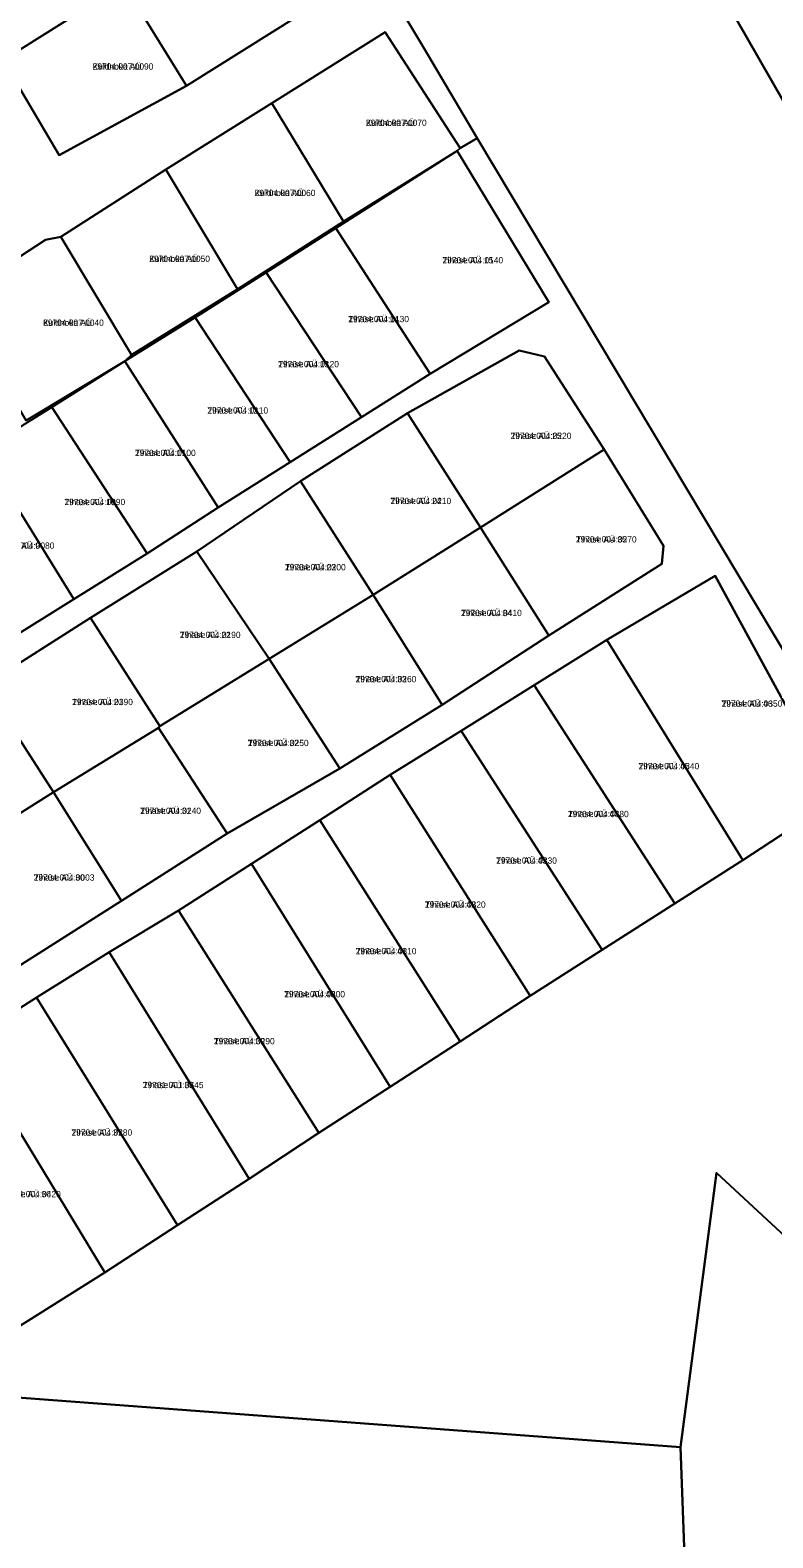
# Model space of a CAD drawing. Extents: x 504287 to 537970, y 6539941 to 6586214.
# Drawn here: x 516728.7 to 516906.1, y 6563396.7 to 6563756.4 of the extents above; entities that cross this region are included whole.
import ezdxf

# ---------------------------------------------------------------- set-up
doc = ezdxf.new("R2010")
doc.units = 0
for name, color, linetype in [('L_AADRESS', 7, 'Continuous'), ('PIIR', 7, 'Continuous'), ('TUNNUS', 7, 'Continuous')]:
    doc.layers.add(name, color=color, linetype=linetype)

msp = doc.modelspace()

# ---------------------------------------------------------------- linework, layer by layer
at = {"layer": 'PIIR'}
for points in [[(517379.78, 6562919.5), (517180.26, 6563268.51), (517112.27, 6563384.86), (516982.09, 6563611.59), (516744.27, 6564025.8), (516744.15, 6564026.01), (516730.68, 6564049.47), (516444.24, 6564548.52), (516445.68, 6564549.17), (516449.01, 6564550.8), (516452.43, 6564551.99), (516458.23, 6564554.15), (516464.7, 6564557.42), (516469.05, 6564559.51), (516471.43, 6564560.88), (516474.52, 6564562.81), (516484.15, 6564569.31), (516486.47, 6564571.24), (516492.75, 6564575.34), (517006.77, 6563683.7), (517111.59, 6563503.08), (517311.3, 6563151.72)], [(516814.57, 6563765.92), (516822.58, 6563752.44), (516835.52, 6563730.64), (516831.44, 6563728.29), (516813.56, 6563755.93), (516786.43, 6563739.01), (516761.12, 6563723.2), (516736.08, 6563707.11), (516732.39, 6563706.39), (516710.76, 6563692.3), (516685.1, 6563676.01), (516659.05, 6563660.05), (516626.42, 6563639.26), (516618.72, 6563651.98), (516652.8, 6563672.2), (516634.4, 6563701.07), (516617.19, 6563729.39), (516602.18, 6563753.59), (516591.84, 6563747.49), (516568.78, 6563733.94), (516566.1, 6563738.35), (516591.67, 6563753.24), (516617.83, 6563768.33)], [(516722.21, 6563610.11), (516739.21, 6563620.66), (516756.7, 6563631.52), (516773.62, 6563642.53), (516790.82, 6563653.37), (516807.85, 6563664.1), (516824.29, 6563674.45), (516852.61, 6563691.56), (516830.7, 6563727.62), (516831.44, 6563728.29), (516835.52, 6563730.64), (516927.25, 6563577.2)], [(516725.02, 6563532.42), (516750.56, 6563548.68), (516775.79, 6563564.73), (516802.71, 6563580.25), (516827.14, 6563595.44), (516852.62, 6563612.01), (516879.6, 6563629.07), (516880.04, 6563633.4), (516865.82, 6563656.34), (516851.54, 6563678.55), (516845.52, 6563679.99), (516818.88, 6563665.04), (516793.27, 6563648.79), (516768.52, 6563632.01), (516743.18, 6563616.21), (516717.81, 6563600.13)], [(516921.33, 6563573.01), (516892.36, 6563626.23), (516866.43, 6563610.95), (516849.15, 6563600.15), (516831.7, 6563589.26), (516814.75, 6563578.77), (516797.92, 6563567.94), (516781.58, 6563557.53), (516764.15, 6563546.36), (516747.57, 6563536.38), (516730.23, 6563525.6), (516713.3, 6563514.8), (516696.5, 6563504), (516670.97, 6563488.02), (516692.12, 6563446.36), (516625.46, 6563445.55), (516501.25, 6563444.05)]]:
    msp.add_lwpolyline(points, dxfattribs=at)
for points in [[(516744.27, 6564025.8), (516982.09, 6563611.59), (516927.25, 6563577.2), (516835.52, 6563730.64), (516822.58, 6563752.44), (516814.57, 6563765.92), (516798.6, 6563792.96), (516760.66, 6563855.96), (516742.75, 6563885.64), (516737.52, 6563882.87), (516722.3, 6563907.76), (516709.28, 6563929.6), (516697.15, 6563950.09), (516684.83, 6563970.67), (516672.52, 6563991.27), (516658.45, 6564008.29), (516673.61, 6564011.42), (516744.15, 6564026.01)], [(516722.29, 6563749.26), (516735.69, 6563726.63), (516766.07, 6563743.18), (516799.74, 6563764.29), (516785.62, 6563789.05), (516771.4, 6563813.09), (516757.06, 6563837.14), (516721.19, 6563815.1), (516692.06, 6563796.82), (516706.99, 6563772.95)], [(516706.99, 6563772.95), (516736.13, 6563791.14), (516751.12, 6563767.4), (516722.29, 6563749.26)], [(516751.12, 6563767.4), (516785.62, 6563789.05), (516799.74, 6563764.29), (516766.07, 6563743.18)], [(516722.29, 6563749.26), (516751.12, 6563767.4), (516766.07, 6563743.18), (516735.69, 6563726.63)], [(516813.56, 6563755.93), (516831.44, 6563728.29), (516830.7, 6563727.62), (516803.59, 6563710.81), (516786.43, 6563739.01)], [(516761.12, 6563723.2), (516786.43, 6563739.01), (516803.59, 6563710.81), (516778.28, 6563694.6)], [(516801.78, 6563709.16), (516830.7, 6563727.62), (516852.61, 6563691.56), (516824.29, 6563674.45)], [(516778.28, 6563694.6), (516752.91, 6563678.97), (516736.08, 6563707.1), (516761.12, 6563723.2)], [(516710.76, 6563692.3), (516732.39, 6563706.39), (516736.08, 6563707.1), (516752.91, 6563678.97), (516751.32, 6563677.47), (516727.82, 6563663.32)], [(516801.78, 6563709.16), (516824.29, 6563674.45), (516807.85, 6563664.1), (516785.14, 6563698.61)], [(516785.14, 6563698.61), (516807.85, 6563664.1), (516790.82, 6563653.37), (516768.11, 6563687.85)], [(516768.11, 6563687.85), (516790.82, 6563653.37), (516773.62, 6563642.53), (516751.32, 6563677.47)], [(516818.88, 6563665.04), (516845.52, 6563679.99), (516851.54, 6563678.55), (516865.82, 6563656.34), (516836.31, 6563637.79)], [(516751.32, 6563677.47), (516773.62, 6563642.53), (516756.7, 6563631.52), (516733.94, 6563666.48)], [(516733.94, 6563666.48), (516756.7, 6563631.52), (516739.21, 6563620.66), (516717.18, 6563656.16)], [(516793.27, 6563648.79), (516818.88, 6563665.04), (516836.31, 6563637.79), (516810.68, 6563621.65)], [(516702.36, 6563647.05), (516717.18, 6563656.16), (516739.21, 6563620.66), (516722.21, 6563610.11), (516700.84, 6563646.09)], [(516836.31, 6563637.79), (516865.82, 6563656.34), (516880.04, 6563633.4), (516879.6, 6563629.07), (516852.62, 6563612.01)], [(516768.52, 6563632.01), (516793.27, 6563648.79), (516810.68, 6563621.65), (516785.8, 6563606.44)], [(516836.31, 6563637.79), (516852.62, 6563612.01), (516827.14, 6563595.44), (516810.68, 6563621.65)], [(516743.18, 6563616.21), (516768.52, 6563632.01), (516785.8, 6563606.44), (516759.74, 6563590.32)], [(516892.36, 6563626.23), (516921.33, 6563573.01), (516898.91, 6563558.38), (516866.43, 6563610.95)], [(516810.68, 6563621.65), (516827.14, 6563595.44), (516802.71, 6563580.25), (516785.8, 6563606.44)], [(516743.18, 6563616.21), (516759.74, 6563590.32), (516759.36, 6563589.97), (516734.29, 6563574.56), (516717.81, 6563600.13)], [(516725.56, 6563446.76), (516746.61, 6563460.01), (516763.92, 6563471.26), (516781.08, 6563482.33), (516797.71, 6563493.29), (516814.71, 6563504.25), (516831.42, 6563515.11), (516848.12, 6563525.98), (516865.33, 6563536.97), (516882.68, 6563548.06), (516898.91, 6563558.38), (516921.33, 6563573.01), (516927.25, 6563577.2), (516982.09, 6563611.59), (517112.27, 6563384.86), (517064.02, 6563325.01), (516892.69, 6563483.77), (516884.06, 6563418.3), (516633.11, 6563437.06), (516625.46, 6563445.55), (516692.12, 6563446.36)], [(516866.43, 6563610.95), (516898.91, 6563558.38), (516882.68, 6563548.06), (516849.15, 6563600.15)], [(516759.36, 6563589.97), (516759.74, 6563590.32), (516785.8, 6563606.44), (516802.71, 6563580.25), (516775.79, 6563564.73)], [(516692.25, 6563584.15), (516717.81, 6563600.13), (516734.29, 6563574.56), (516708.64, 6563558.48)], [(516849.15, 6563600.15), (516882.68, 6563548.06), (516865.33, 6563536.97), (516831.7, 6563589.26)], [(516734.29, 6563574.56), (516759.36, 6563589.97), (516775.79, 6563564.73), (516750.56, 6563548.68)], [(516831.7, 6563589.26), (516865.33, 6563536.97), (516848.12, 6563525.98), (516814.75, 6563578.77)], [(516814.75, 6563578.77), (516848.12, 6563525.98), (516831.42, 6563515.11), (516797.92, 6563567.94)], [(516734.29, 6563574.56), (516750.56, 6563548.68), (516725.02, 6563532.42), (516708.64, 6563558.48)], [(516797.92, 6563567.94), (516831.42, 6563515.11), (516814.71, 6563504.25), (516781.58, 6563557.53)], [(516781.58, 6563557.53), (516814.71, 6563504.25), (516797.71, 6563493.29), (516764.15, 6563546.36)], [(516781.08, 6563482.33), (516747.57, 6563536.38), (516764.15, 6563546.36), (516797.71, 6563493.29)], [(516747.57, 6563536.38), (516781.08, 6563482.33), (516763.92, 6563471.26), (516730.23, 6563525.6)], [(516730.23, 6563525.6), (516763.92, 6563471.26), (516746.61, 6563460.01), (516713.3, 6563514.8)], [(516713.3, 6563514.8), (516746.61, 6563460.01), (516725.56, 6563446.76), (516696.5, 6563504)], [(516892.69, 6563483.77), (517064.02, 6563325.01), (517030.85, 6563238.92), (517015.03, 6563245.02), (516900.03, 6563265.88), (516888.62, 6563294.88), (516884.06, 6563418.3)], [(516501.25, 6563444.05), (516625.46, 6563445.55), (516633.11, 6563437.06), (516884.06, 6563418.3), (516888.62, 6563294.88), (516865.54, 6563151.5), (516892.22, 6563104.11), (516896.52, 6563093.71), (516896.31, 6563070.84), (516900.68, 6563071.4), (516864.48, 6563024.66), (516715.46, 6563293.57), (516424.36, 6563426.81), (516408.82, 6563458.96)]]:
    msp.add_lwpolyline(points, close=True, dxfattribs=at)

# ---------------------------------------------------------------- texts
at = {"layer": 'L_AADRESS'}
for s, p in [('Kuldnoka AÜ 9', (516743.66, 6563747.01)), ('Kuldnoka AÜ 7', (516808.93, 6563733.58)), ('Kuldnoka AÜ 6', (516782.36, 6563716.84)), ('Kuldnoka AÜ 5', (516757.18, 6563701.13)), ('Tihase AÜ 15', (516827.2, 6563700.79)), ('Tihase AÜ 14', (516804.71, 6563686.75)), ('Kuldnoka AÜ 4', (516731.83, 6563685.88)), ('Tihase AÜ 13', (516787.98, 6563675.99)), ('Tihase AÜ 12', (516771.07, 6563664.94)), ('Tihase AÜ 25', (516843.5, 6563658.89)), ('Tihase AÜ 11', (516753.78, 6563654.81)), ('Tihase AÜ 10', (516736.94, 6563643.09)), ('Tihase AÜ 24', (516814.79, 6563643.34)), ('Tihase AÜ 35', (516859.08, 6563634.18)), ('Tihase AÜ 9', (516720.03, 6563632.68)), ('Tihase AÜ 23', (516789.6, 6563627.53)), ('Tihase AÜ 34', (516831.65, 6563616.61)), ('Tihase AÜ 22', (516764.49, 6563611.38)), ('Tihase AÜ 33', (516806.47, 6563600.83)), ('Tihase AÜ 21', (516738.78, 6563595.37)), ('Tihase AÜ 46', (516893.88, 6563594.98)), ('Tihase AÜ 32', (516780.74, 6563585.59)), ('Tihase AÜ 45', (516874.03, 6563580.07)), ('Tihase AÜ 31', (516755.04, 6563569.42)), ('Tihase AÜ 44', (516857.19, 6563568.64)), ('Tihase AÜ 43', (516840.04, 6563557.53)), ('Tihase AÜ 30', (516729.6, 6563553.48)), ('Tihase AÜ 42', (516823.02, 6563547.02)), ('Tihase AÜ 41', (516806.5, 6563535.93)), ('Tihase AÜ 40', (516789.43, 6563525.64)), ('Tihase AÜ 39', (516772.64, 6563514.44)), ('Tihase AÜ 38', (516755.65, 6563503.97)), ('Tihase AÜ 37', (516738.61, 6563492.63)), ('Tihase AÜ 36', (516721.55, 6563477.94))]:
    msp.add_text(s, height=1.5, dxfattribs=at).set_placement(p)
at = {"layer": 'TUNNUS'}
for s, p in [('29704:007:0090', (516743.66, 6563747.01)), ('29704:007:0070', (516808.93, 6563733.58)), ('29704:007:0060', (516782.36, 6563716.84)), ('29704:007:0050', (516757.18, 6563701.13)), ('29704:004:0140', (516827.2, 6563700.79)), ('29704:007:0040', (516731.83, 6563685.88)), ('29704:004:0130', (516804.71, 6563686.75)), ('29704:004:0120', (516787.98, 6563675.99)), ('29704:004:0110', (516771.07, 6563664.94)), ('29704:004:0220', (516843.5, 6563658.89)), ('29704:004:0100', (516753.78, 6563654.81)), ('29704:004:0090', (516736.94, 6563643.09)), ('29704:004:0210', (516814.79, 6563643.34)), ('29704:004:0270', (516859.08, 6563634.18)), ('29704:004:0080', (516720.03, 6563632.68)), ('29704:004:0200', (516789.6, 6563627.53)), ('29704:004:0410', (516831.65, 6563616.61)), ('29704:004:0190', (516764.49, 6563611.38)), ('29704:004:0260', (516806.47, 6563600.83)), ('29704:004:0390', (516738.78, 6563595.37)), ('29704:004:0350', (516893.88, 6563594.98)), ('29704:004:0250', (516780.74, 6563585.59)), ('29704:004:0340', (516874.03, 6563580.07)), ('29704:004:0240', (516755.04, 6563569.42)), ('29704:004:0380', (516857.19, 6563568.64)), ('29704:004:0330', (516840.04, 6563557.53)), ('29704:004:0003', (516729.6, 6563553.48)), ('29704:004:0320', (516823.02, 6563547.02)), ('29704:004:0310', (516806.5, 6563535.93)), ('29704:004:0300', (516789.43, 6563525.64)), ('29704:004:0290', (516772.64, 6563514.44)), ('29701:001:0545', (516755.65, 6563503.97)), ('29704:004:0280', (516738.61, 6563492.63)), ('29704:004:0420', (516721.55, 6563477.94))]:
    msp.add_text(s, height=1.5, dxfattribs=at).set_placement(p)

doc.saveas('drawing.dxf')
